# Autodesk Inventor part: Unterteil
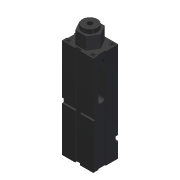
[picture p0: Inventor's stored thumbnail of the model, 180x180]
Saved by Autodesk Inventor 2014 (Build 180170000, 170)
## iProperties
Created: 2014-03
Part Number: Unterteil
Material: Generisch
Document SubType Name: Modeling
Designer: e_dammj
Density: 1 g/cm^3
Appearance: Vorgabe
Sending System: SolidWorks 2011
Last Author: e_boekem
Author: e_dammj
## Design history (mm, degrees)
node "Unterteil.ipt1"
node "Aufsatz-Linear austragen3"
node "Basis1"
